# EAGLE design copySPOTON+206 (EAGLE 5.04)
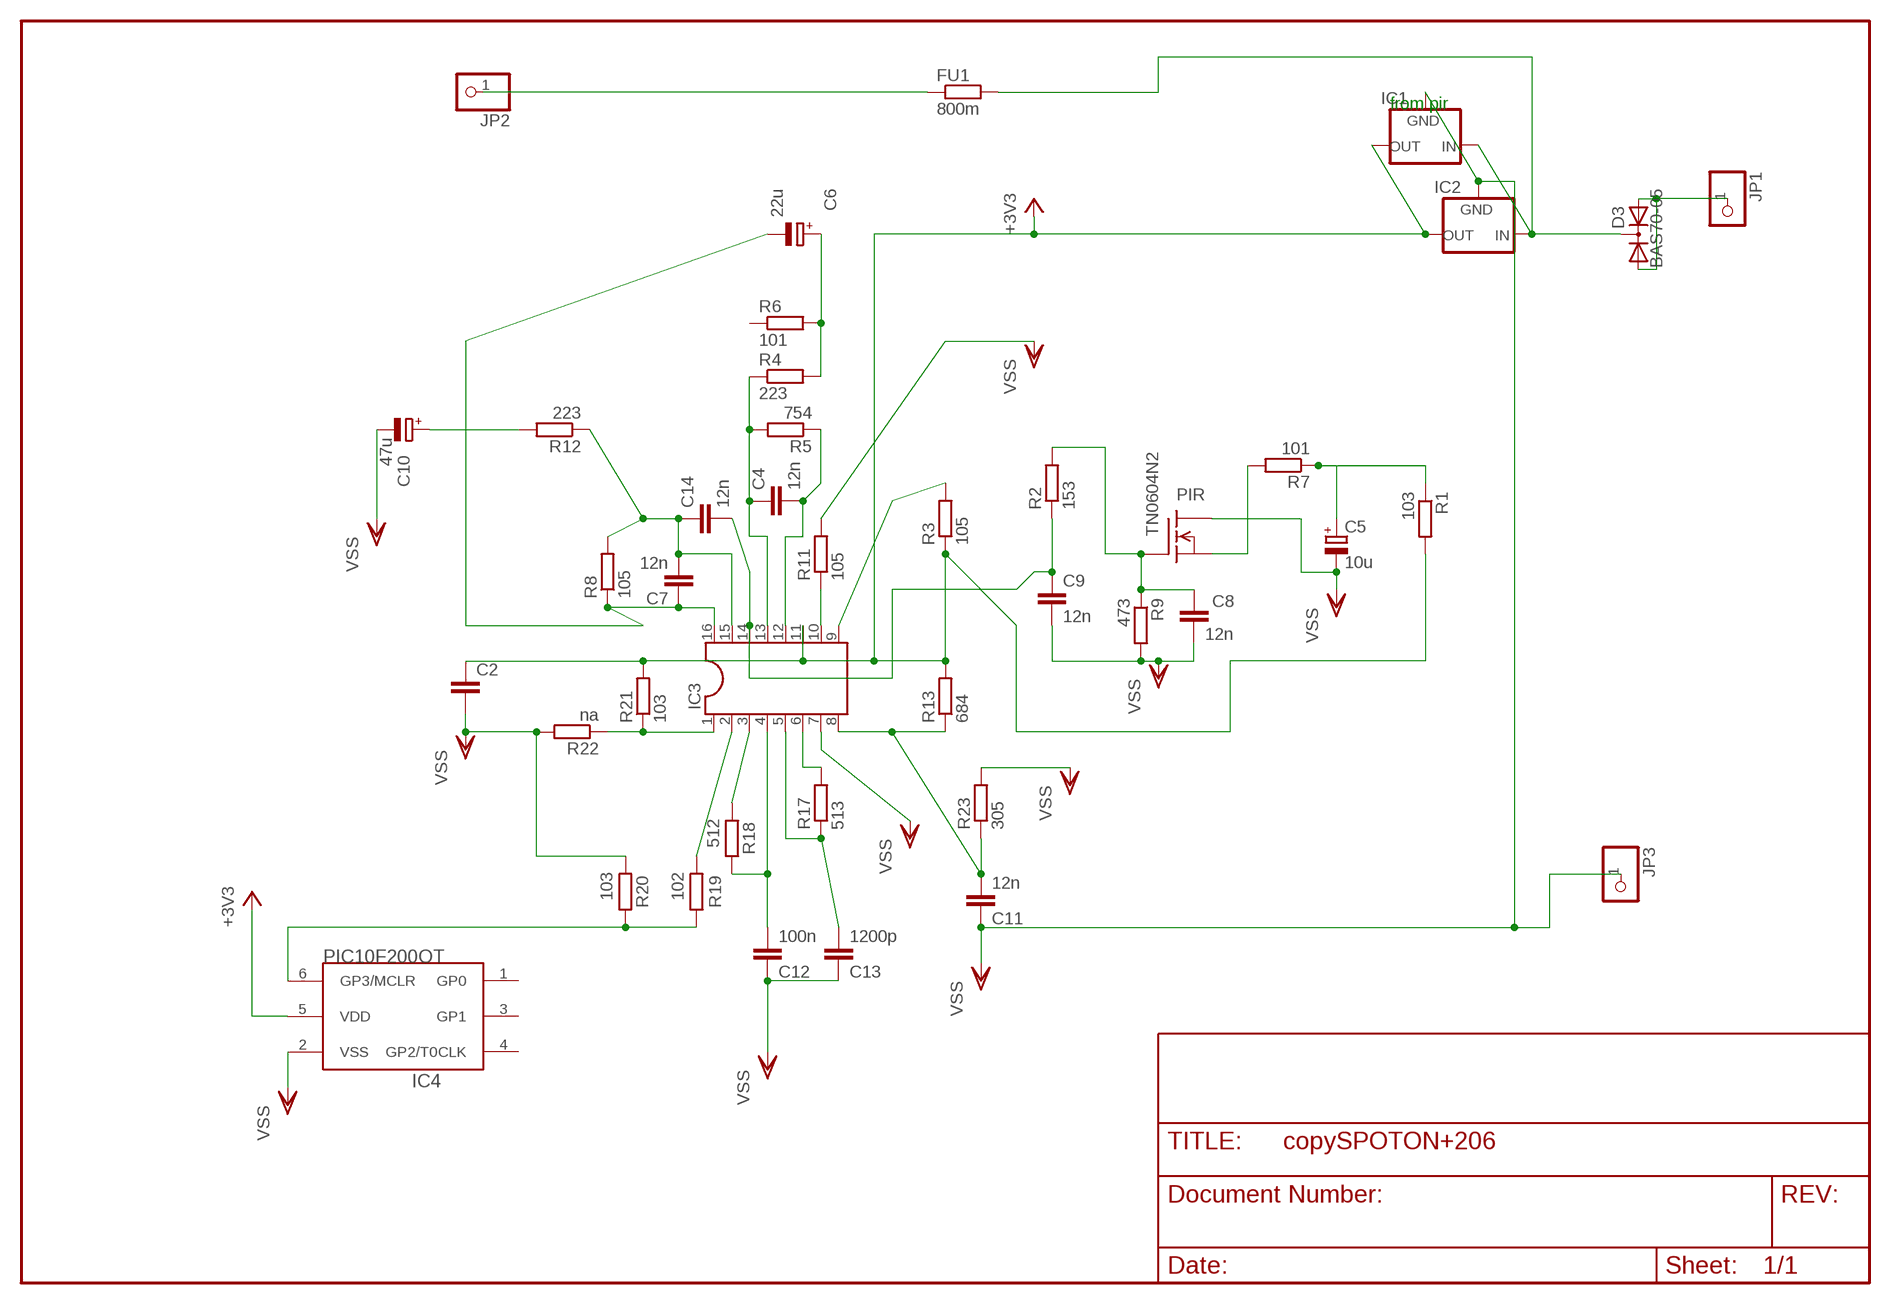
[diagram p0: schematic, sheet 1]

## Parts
C2  C-EUC0805  [C0805]
C4  12n  C-EUC0805  [C0805]
C5  10u  CPOL-EUE2.5-5  [E2,5-5]
C6  22u  CPOL-EUE2.5-5  [E2,5-5]
C7  12n  C-EUC0805  [C0805]
C8  12n  C-EUC0805  [C0805]
C9  12n  C-EUC0805  [C0805]
C10  47u  CPOL-EUE2.5-5  [E2,5-5]
C11  12n  C-EUC0805  [C0805]
C12  100n  C-EUC0805  [C0805]
C13  1200p  C-EUC0805  [C0805]
C14  12n  C-EUC0805  [C0805]
D3  BAS70-05  [SOT23]
FU1  800m  R-EU_0204/5  [0204/5]
IC1  XC63FPT  [TO92]
IC2  XC63FPP  [SOT89R]
IC3  DIL16SO16  [SO16]
IC4  PIC10F200OT  [SOT23-6]
JP1  PINHD-1X1  [1X01]
JP2  PINHD-1X1  [1X01]
JP3  PINHD-1X1  [1X01]
PIR  TN0604N2  [TO-39]
R1  103  R-EU_R0805  [R0805]
R2  153  R-EU_R0805  [R0805]
R3  105  R-EU_R0805  [R0805]
R4  223  R-EU_R0805  [R0805]
R5  754  R-EU_R0805  [R0805]
R6  101  R-EU_R0805  [R0805]
R7  101  R-EU_R0805  [R0805]
R8  105  R-EU_R0805  [R0805]
R9  473  R-EU_R0805  [R0805]
R11  105  R-EU_R0805  [R0805]
R12  223  R-EU_R0805  [R0805]
R13  684  R-EU_R0805  [R0805]
R17  513  R-EU_R0805  [R0805]
R18  512  R-EU_R0805  [R0805]
R19  102  R-EU_R0805  [R0805]
R20  103  R-EU_R0805  [R0805]
R21  103  R-EU_R0805  [R0805]
R22  na  R-EU_R0805  [R0805]
R23  305  R-EU_R0805  [R0805]

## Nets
+3V3: C2.1 IC1.3(OUT) IC2.3(OUT) IC3.11 IC4.5(VDD) R1.2 R3.1 R13.2 R21.2
N$4: FU1.1 JP2.1
N$7: D3.1(A1) D3.2(A2) JP1.1
N$8: D3.3(C) FU1.2 IC1.2(IN) IC2.2(IN)
N$10: IC3.9 R3.2
N$11: IC3.1 R21.1 R22.1
N$19: IC4.6(GP3/MCLR) R19.1 R20.1
N$24: IC3.2 R19.2
N$25: C12.1 IC3.4 R18.1
N$27: IC3.3 R18.2
N$28: C11.1 IC3.8 R13.1 R23.1
N$30: C13.1 IC3.5 R17.1
N$31: IC3.6 R17.2
N$32: IC3.10 R11.1
N$34: C4.2 IC3.12 R5.1
N$35: C4.1 IC3.13 R4.1 R5.2
N$37: C6.+ R4.2 R6.2
N$39: C9.1 C14.2 IC3.14 R2.1
N$40: C7.2 C14.1 IC3.15 R8.2 R12.1
N$41: C6.- C7.1 IC3.16 R8.1
N$42: PIR.1(S) R7.2
N$43: C5.+ R1.1 R7.1
N$44: C10.+ R12.2
N$46: C8.1 PIR.2(G) R2.2 R9.1
VSS: C2.2 C5.- C8.2 C9.2 C10.- C11.2 C12.2 C13.2 IC1.1(GND) IC2.1(GND) IC3.7 IC4.2(VSS) JP3.1 PIR.3(D) R9.2 R11.2 R20.2 R22.2 R23.2
Unconnected: IC4.1(GP0) IC4.3(GP1) IC4.4(GP2/T0CLK) R6.1

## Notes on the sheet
- from pir

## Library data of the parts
C2 C4 C7-C9 C11-C14 = rcl-2:C-EU: CAPACITOR, European symbol
C5 C6 C10 = rcl:CPOL-EU: POLARIZED CAPACITOR, European symbol
D3 = diode-1:BAS70-05: Silicon Schottky Diodes General-purpose diode for high-speed switching
FU1 = rcl:R-EU_: RESISTOR, European symbol
IC1 IC2 = v-reg:XC63FP: Positiv Voltage Regulators www.torex.co.jp/english/product/pro02/pdf/0201_xc62fp.pdf
IC3 = ic-package:DIL16: Dual In Line / Socket
IC4 = microchip-5:PIC10F20*: uPC nW 0,25/0,5k Program Flash memory
JP1-JP3 = pinhead:PINHD-1X1: PIN HEADER
PIR = transistor-fet:TN0604N2: N-Channel Enhancement MOSFET 40V; 4A; 0,85Ohm
R1-R9 R11-R13 R17-R23 = rcl-2:R-EU_: RESISTOR, European symbol

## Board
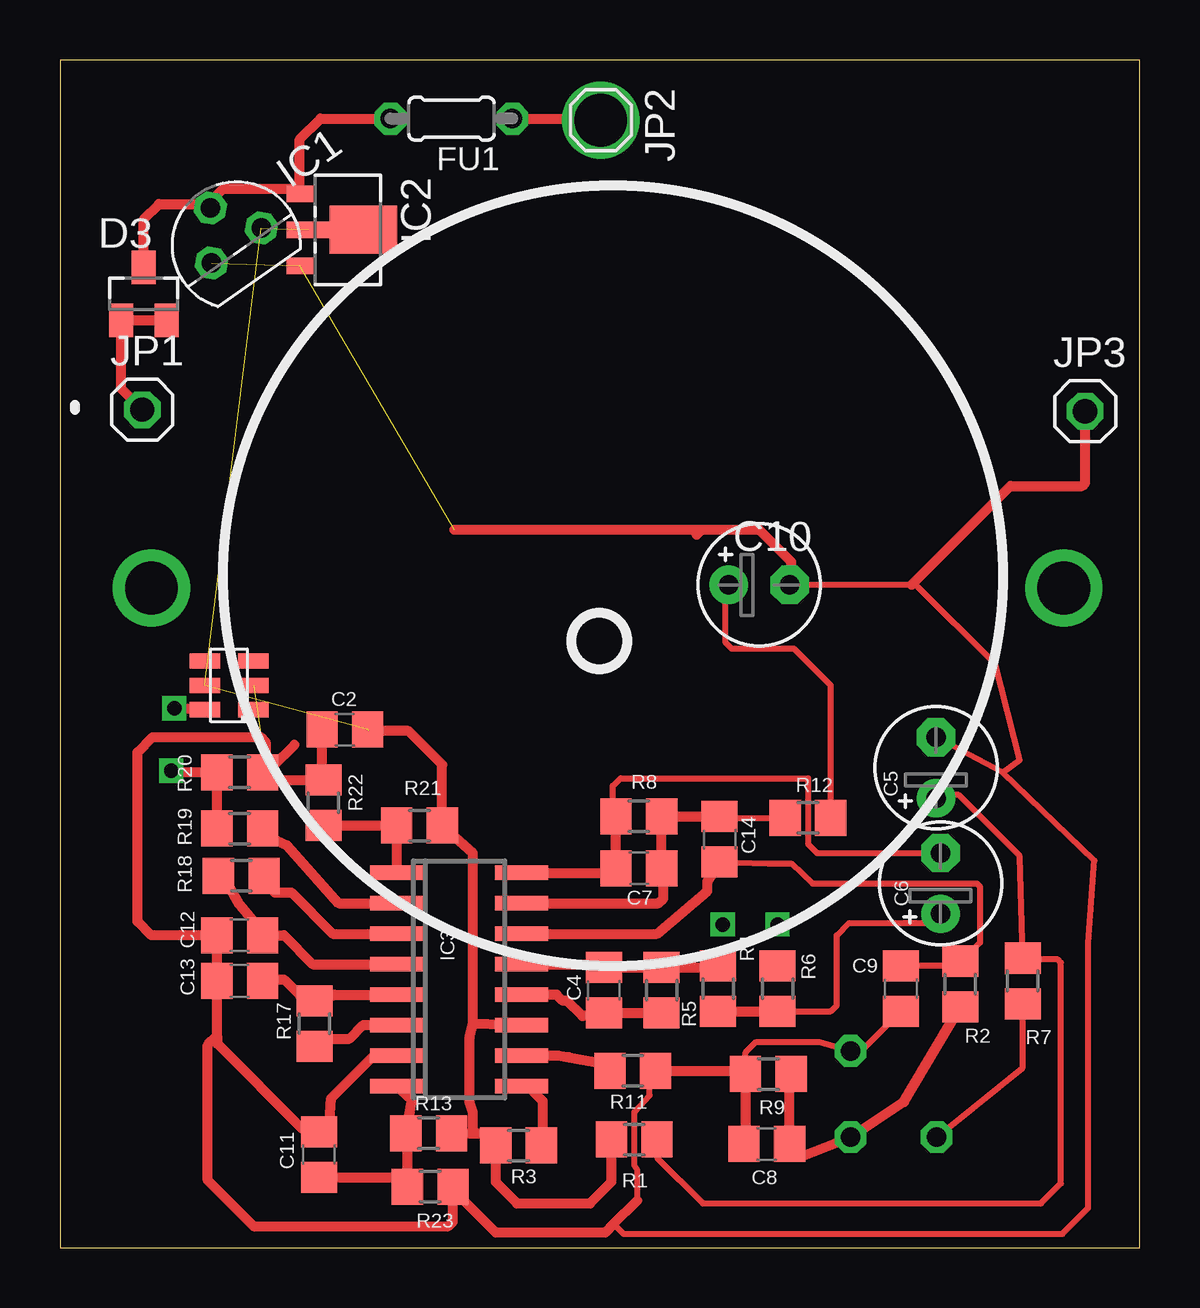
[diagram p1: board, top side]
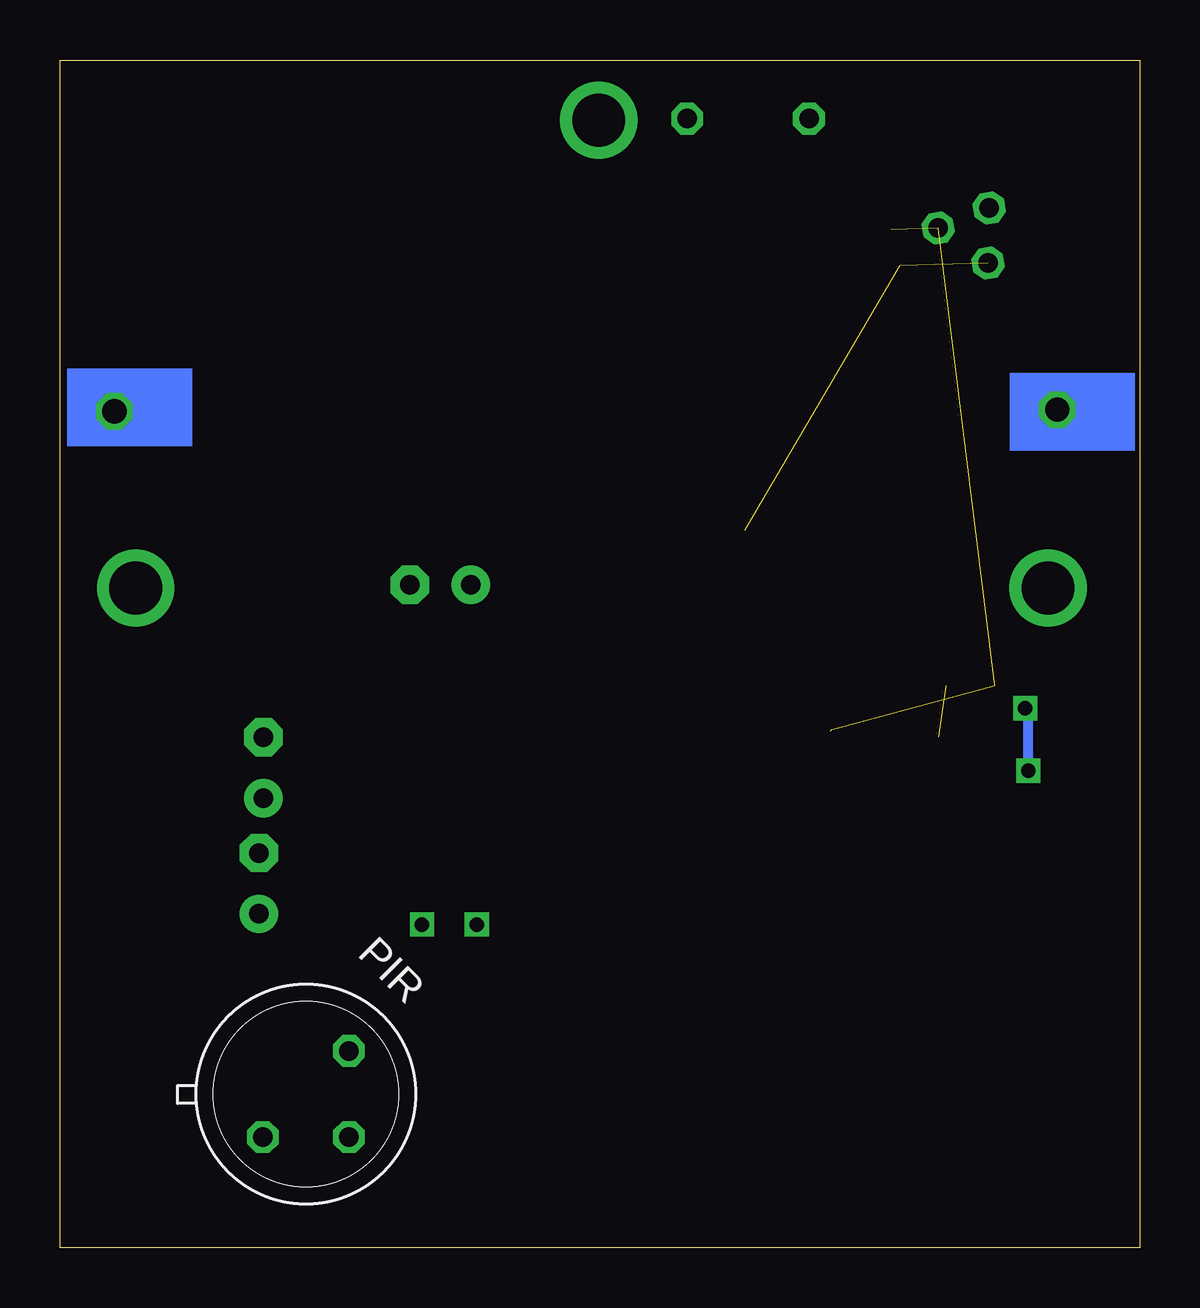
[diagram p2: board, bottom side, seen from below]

Size 45 x 49.5 mm. Coordinates in mm from the lower left corner, seen from the top.
Outline: 0,0 45,0 45,49.5 0,49.5 0,0
Copper layers (1*16): Top 0.035mm / dielectric 1.5mm / Bottom 0.035mm
Design rules "default": minimum track width 10mil, minimum drill 24mil, track to track 8mil, track to pad 8mil, pad to pad 8mil, via to via 8mil, smd to smd 8mil, copper to edge 40mil, drill to drill 8mil, minimum pad ring 10mil, minimum via ring 8mil, stop-mask expansion 4mil, vias tented up to drill 0mil, thermal gap 10mil

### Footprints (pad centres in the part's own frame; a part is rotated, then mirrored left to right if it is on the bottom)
C0805 = smd 1.3 x 1.5: 1 -0.95,0; 2 0.95,0
E2,5-5 = drill 0.813 pad 1.6 round: + -1.27,0 | drill 0.813 pad 1.6 octagon: - 1.27,0
SOT23 = smd 1 x 1.4: 1 -0.95,-1.1; 2 0.95,-1.1; 3 0,1.1
0204/5 = drill 0.813 octagon: 1 -2.54,0; 2 2.54,0
TO92 = drill 0.813 octagon: 1 -1.27,0; 2 0,1.905; 3 1.27,0
SOT89R = smd 0.7 x 1.1: 1 1.5,-1.75; 2 -1.5,-1.75 | smd 0.7 x 1.8: 3 0,-1.4 | smd 2 x 2.8: 4 0,0.9
SO16 = smd 0.6 x 2.2: 1 -4.445,-2.6; 2 -3.175,-2.6; 3 -1.905,-2.6; 4 -0.635,-2.6; 5 0.635,-2.6; 6 1.905,-2.6; 7 3.175,-2.6; 8 4.445,-2.6; 9 4.445,2.6; 10 3.175,2.6; 11 1.905,2.6; 12 0.635,2.6; 13 -0.635,2.6; 14 -1.905,2.6; 15 -3.175,2.6; 16 -4.445,2.6
SOT23-6 = smd 0.635 x 1.27: 1 -1.016,-1.016; 2 0,-1.016; 3 1.016,-1.016; 4 1.016,1.016; 5 0,1.016; 6 -1.016,1.016
1X01 = drill 1.016 octagon: 1 0,0
TO-39 = drill 0.813 octagon: 1 0,-2.54; 2 2.54,0; 3 0,2.54
R0805 = smd 1.3 x 1.5: 1 -0.95,0; 2 0.95,0

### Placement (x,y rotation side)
C2  11.87,21.59 180 top
C4  22.67,10.73 270 top
C5  36.51,20 90 top
C6  36.7,15.18 90 top
C7  24.13,15.81 0 top
C8  29.46,4.32 180 top
C9  35.05,10.79 270 top
C10  29.15,27.62 0 top
C11  10.79,3.87 90 top
C12  7.49,13.02 180 top
C13  7.49,11.11 180 top
C14  27.5,17.02 270 top
D3  3.49,39.75 0 top
FU1  16.32,47.05 180 top
IC1  7.35,41.77 35 top
IC2  11.75,42.42 270 top
IC3  16.64,11.18 270 top
IC4  7.05,23.43 90 top
JP1  3.43,34.92 0 top
JP2  22.54,46.99 270 top
JP3  42.74,34.86 0 top
PIR  34.75,6.4 315 bottom
R1  23.94,4.51 180 top
R2  37.53,10.99 270 top
R3  19.11,4.25 0 top
R4  27.43,10.79 270 top
R5  25.08,10.73 90 top
R6  29.91,10.79 270 top
R7  40.13,11.11 270 top
R8  24.13,17.97 0 top
R9  29.53,7.24 180 top
R11  23.88,7.37 0 top
R12  31.18,17.91 0 top
R13  15.37,4.76 0 top
R17  10.6,9.33 270 top
R18  7.56,15.49 0 top
R19  7.49,17.46 0 top
R20  7.49,19.81 0 top
R21  14.99,17.59 0 top
R22  10.99,18.54 90 top
R23  15.43,2.54 0 top

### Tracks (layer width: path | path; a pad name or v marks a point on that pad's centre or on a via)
+3V3  (4 unrouted)
  Top 0.406: 17.21,4.76 17.66,4.76 R3.1 18.16,2.73 19.05,1.84 22.1,1.84 22.99,2.73 R1.2 | R13.2 17.21,4.76 | 17.21,9.34 IC3.11 | 17.21,9.34 17.08,8.76 17.08,6.03 17.21,5.59 17.21,4.76 | 17.21,9.34 17.21,16.44 R21.2 15.94,20.13 14.54,21.53 12.89,21.53
N$1  (via drill 0.6)
  other vias: 27.62,13.46
N$2  (via drill 2.2)
  other vias: 3.81,27.5
N$3  (via drill 2.2)
  other vias: 41.85,27.5
N$4
  Top 0.406: FU1.1 22.48,47.05 JP2.1
N$5  (via drill 2.2)
  other vias: 22.54,46.99
N$6  (via drill 0.6)
  other vias: 29.91,13.46
N$7
  Top 0.406: JP1.1 2.54,35.81 D3.1 D3.2
N$8
  Top 0.406: D3.3 3.49,42.86 4.13,43.5 6.09,43.5 IC1.2 6.26,43.6 6.79,44.13 9.78,44.13 IC2.2 10,46.19 10.86,47.05 FU1.2
N$10
  Top 0.406: IC3.9 19.49,6.73 20.13,6.1 20.13,4.32 R3.2
N$11
  Top 0.406: R22.1 R21.1 IC3.1
N$19  (via drill 0.6)
  Top 0.406: R19.1 R20.1 4.7,19.81 v4.64,19.88 | v4.76,22.48 5.97,22.48 IC4.6
  Bottom 0.406: v4.64,19.88 4.64,22.35 v4.76,22.48
N$24
  Top 0.406: IC3.2 11.62,14.35 9.46,16.76 8.82,17.08 R19.2
N$25
  Top 0.406: IC3.4 10.54,11.81 9.34,13.02 C12.1 8,13.65 7.49,14.29 7.05,15.05 R18.1
N$27
  Top 0.406: IC3.3 11.37,13.08 9.65,14.8 8.95,14.8 R18.2
N$28
  Top 0.406: IC3.8 14.67,6.16 R13.1 14.48,4.7 R23.1 14.1,2.92 C11.1
N$30
  Top 0.406: IC3.5 11.43,10.54 R17.1 10.54,9.97 9.34,11.18 8.51,11.18 C13.1
N$31
  Top 0.406: IC3.6 12.64,9.27 12.06,8.7 10.92,8.7 R17.2
N$32
  Top 0.406: IC3.10 20.77,8 21.21,7.94 22.61,7.68 R11.1
N$34
  Top 0.406: IC3.12 20.7,10.54 20.95,10.29 21.14,10.29 21.78,9.65 22.54,9.65 C4.2 R5.1
N$35
  Top 0.406: IC3.13 22.54,11.81 C4.1 R5.2 27.37,11.68 R4.1
N$37
  Top 0.254: R6.2 32.13,9.85 32.38,10.1 32.38,13.02 32.89,13.53 36.32,13.53 C6.+
  Top 0.406: R4.2 R6.2
N$39
  Top 0.254: C14.2 29.53,16 30.48,16 31.37,15.18 38.23,15.18 38.35,15.05 38.35,12.7 37.59,11.94 R2.1 37.34,11.74 C9.1
  Top 0.406: IC3.14 24.89,13.08 26.99,14.86 26.99,15.24 C14.2
N$40
  Top 0.254: R12.1 27.56,17.91 C14.1
  Top 0.406: IC3.15 24.96,14.35 25.15,14.54 25.15,15.36 C7.2 R8.2 C14.1
N$41
  Top 0.254: C6.- 31.56,16.45 31.18,16.83 31.18,19.56 23.37,19.56 23.05,19.24 23.05,18.1 R8.1
  Top 0.406: IC3.16 22.99,15.62 C7.1 R8.1
N$42
  Top 0.254: R7.2 40.13,7.49 PIR.1
N$43
  Top 0.254: C5.+ 36.64,18.86 37.47,18.86 40.01,16.32 R7.1 40.19,12 41.59,12 41.72,11.87 41.72,2.67 40.89,1.84 26.8,1.84 24.89,3.75 R1.1
N$44
  Top 0.254: R12.2 32.13,23.43 30.61,24.96 28,24.96 27.75,25.21 27.75,27.5 C10.+
N$46
  Top 0.406: R2.2 35.18,6.07 PIR.2 30.93,3.8 C8.1 30.41,7.18 R9.1
VSS  (3 unrouted)
  Top 0.254: 24.07,1.97 24.07,3.24 23.94,3.43 23.94,5.65 24.57,6.35 24.57,7.11 R11.2 | R9.2 28.58,8.13 29.02,8.57 31.66,8.57 PIR.3 32.85,7.64 C9.2 | 39.31,19.81 43.12,16.13 42.86,12.7 42.86,1.65 41.78,0.57 23.5,0.57 23.08,0.98 | 39.31,19.81 C5.- | C10.- 35.5,27.62 35.69,27.62 38.99,24.32 40.01,20.32 39.31,19.81
  Top 0.406: 6.54,8.83 6.54,8.51 10.1,4.95 10.66,4.95 C11.2 11.24,5.27 11.3,6.22 13.02,7.94 IC3.7 | 6.54,8.83 C13.2 C12.2 3.81,13.02 3.24,13.59 3.24,20.64 3.87,21.27 8.38,21.27 8.57,21.08 8.57,20.38 8.89,20.07 | C2.2 10.93,19.55 R22.2 8.76,19.49 R20.2 8.64,19.81 8.89,20.07 | R11.2 28.45,7.37 R9.2 28.58,4.38 C8.2 | 6.54,8.83 6.16,8.44 6.16,2.79 8.06,0.89 16.19,0.89 16.38,1.08 R23.2 16.38,2.42 18.16,0.64 22.73,0.64 23.08,0.98 24.07,1.97 | JP3.1 42.74,31.88 42.61,31.75 39.62,31.75 35.5,27.62 | 26.73,29.91 29.15,29.91 30.48,28.57 30.48,27.69 C10.- | 26.73,29.91 16.45,29.91 | 8.89,20.07 9.78,20.95 | 26.73,29.91 26.54,29.72
(copper drawn outside any net)
  shapes: Bottom area x2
